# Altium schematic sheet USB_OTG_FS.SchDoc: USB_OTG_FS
size A4; DocumentNumber: MB1167; Revision: B.1; SheetNumber: 9; SheetTotal: 17; Project: STM327x6G-EVAL
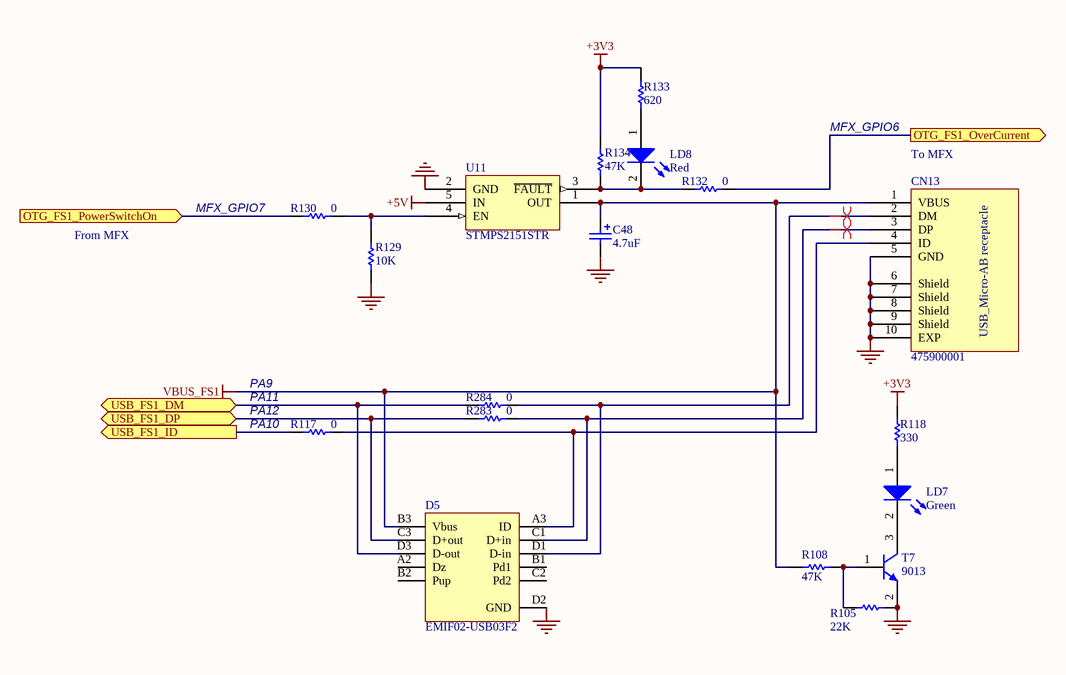
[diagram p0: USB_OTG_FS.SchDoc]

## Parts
C48  4.7uF  [TAN-A]
CN13  475900001  [MOLEX_47590001]
D5  EMIF02-USB03F2  [BGA11_0R5_1R57X2R07]
LD7  Green  [0603D]
LD8  Red  [0603D]
R105  22K  [0603R]
R108  47K  [0603R]
R117  0  [0603R]
R118  330  [0603R]
R129  10K  [0603R]
R130  0  [0603R]
R132  0  [0603R]
R133  620  [0603R]
R134  47K  [0603R]
R283  0  [0603R]
R284  0  [0603R]
T7  9013  [SOT-23]
U11  STMPS2151STR  [SOT23-5]

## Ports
OTG_FS1_OverCurrent (out), OTG_FS1_PowerSwitchOn (in), USB_FS1_DM (bidir), USB_FS1_DP (bidir), USB_FS1_ID (out)

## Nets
+3V3: R118.2 R133.2 R134.1
+5V: U11.5(IN)
GND: C48.2 CN13.5(GND) CN13.6(Shield) CN13.7(Shield) CN13.8(Shield) CN13.9(Shield) CN13.10(EXP) D5.D2(GND) R105.1 R129.1 T7.2(E) U11.2(GND)
VBUS_FS1: C48.1 CN13.1(VBUS) D5.B3(Vbus) R108.1 U11.1(OUT)
OTG_FS1_OverCurrent: R132.1 ; port OTG_FS1_OverCurrent
OTG_FS1_PowerSwitchOn: R130.2 ; port OTG_FS1_PowerSwitchOn
USB_FS1_DM: D5.D3(D-out) R284.2 ; port USB_FS1_DM
USB_FS1_DP: D5.C3(D+out) R283.2 ; port USB_FS1_DP
USB_FS1_ID: R117.2 ; port USB_FS1_ID
NetCN13_2: CN13.2(DM) D5.D1(D-in) R284.1
NetCN13_3: CN13.3(DP) D5.C1(D+in) R283.1
NetCN13_4: CN13.4(ID) D5.A3(ID) R117.1
NetLD7_1: LD7.1(A) R118.1
NetLD7_2: LD7.2(K) T7.3(C)
NetLD8_1: LD8.1(A) R133.1
NetLD8_2: LD8.2(K) R132.2 R134.2 U11.3(~{FAULT})
NetR105_2: R105.2 R108.2 T7.1(B)
NetR129_2: R129.2 R130.1 U11.4(EN)

Not connected (* = marked no-connect by the designer): D5 A2(Dz) B1(Pd1) B2(Pup) C2(Pd2)

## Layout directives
differential pair: NetCN13_2, NetCN13_3

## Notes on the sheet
- MFX_GPIO6
- (near R130) MFX_GPIO7
- (near CN13) To MFX
- From MFX
- PA9
- (near R117) PA11
- (near R117) PA12
- (near R117) PA10

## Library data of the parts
C48 = Cap Pol1: Polarized Capacitor (Radial); Value: 47uF
LD7 LD8 = LED2: Typical RED, GREEN, YELLOW, AMBER GaAs LED
R105 R108 R118 R134 = res1: Resistor; Value: 1K
R117 R129 R130 R132 R133 R283 R284 = Res1: Resistor; Value: 1K
T7 = NPN: NPN Bipolar Transistor; Code - JEDEC: TO-226-AA
U11 = STMPS2141STR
